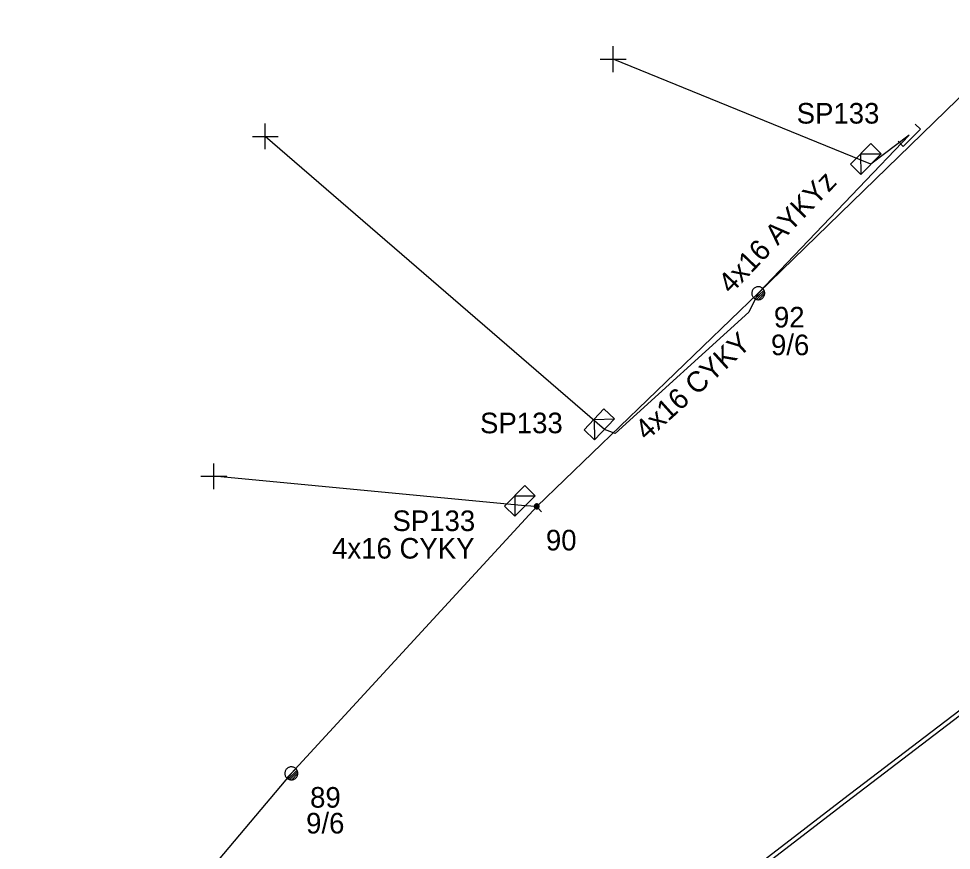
# Model space of a CAD drawing. Extents: x -748492 to -735633, y -1146251 to -1139940.
# Drawn here: x -742254.66 to -742209.4, y -1141162.91 to -1141122.53 of the extents above; entities that cross this region are included whole.
import ezdxf

# ---------------------------------------------------------------- set-up
doc = ezdxf.new("R2010")
doc.units = 0
for name, color, linetype in [('Vrstva 1', 7, 'Continuous'), ('Vrstva 12', 7, 'Continuous'), ('Vrstva 13', 7, 'Continuous'), ('Vrstva 14', 7, 'Continuous'), ('Vrstva 2', 7, 'Continuous'), ('Vrstva 31', 7, 'Continuous'), ('Vrstva 33', 7, 'Continuous'), ('Vrstva 34', 7, 'Continuous'), ('Vrstva 5', 7, 'Continuous'), ('Vrstva 52', 7, 'Continuous'), ('Vrstva 54', 7, 'Continuous'), ('Vrstva 55', 7, 'Continuous'), ('Vrstva 59', 7, 'Continuous'), ('Vrstva 9', 7, 'Continuous')]:
    doc.layers.add(name, color=color, linetype=linetype)

# ---------------------------------------------------------------- blocks, each defined once
blk = doc.blocks.new('NN440')
at = {"layer": 'Vrstva 2'}
for points in [[(0.631, -0.004), (0.627, 0.062), (0.617, 0.127), (0.6, 0.191), (0.577, 0.252), (0.547, 0.311), (0.511, 0.366), (0.469, 0.417), (0.423, 0.464), (0.371, 0.505), (0.316, 0.542), (0.257, 0.571), (0.196, 0.595), (0.132, 0.612), (0.067, 0.622), (0.001, 0.626), (-0.065, 0.622), (-0.13, 0.612), (-0.194, 0.595), (-0.255, 0.571), (-0.314, 0.542), (-0.369, 0.505), (-0.42, 0.464), (-0.467, 0.417), (-0.509, 0.366), (-0.544, 0.311), (-0.574, 0.252), (-0.598, 0.191), (-0.615, 0.127), (-0.626, 0.062), (-0.629, -0.004), (-0.626, -0.07), (-0.615, -0.135), (-0.598, -0.199), (-0.574, -0.26), (-0.544, -0.319), (-0.509, -0.374), (-0.467, -0.426), (-0.42, -0.472), (-0.369, -0.514), (-0.314, -0.55), (-0.255, -0.58), (-0.194, -0.603), (-0.13, -0.62), (-0.065, -0.631), (0.001, -0.634), (0.067, -0.631), (0.132, -0.62), (0.196, -0.603), (0.257, -0.58), (0.316, -0.55), (0.371, -0.514), (0.423, -0.472), (0.469, -0.426), (0.511, -0.374), (0.547, -0.319), (0.577, -0.26), (0.6, -0.199), (0.617, -0.135), (0.627, -0.07), (0.631, -0.004)], [(-0.631, 0), (0.629, 0)], [(-0.601, -0.177), (0.57, -0.177)], [(-0.513, -0.325), (0.501, -0.325)], [(-0.375, -0.473), (0.353, -0.473)]]:
    blk.add_lwpolyline(points, dxfattribs=at)
blk = doc.blocks.new('NN800')
at = {"layer": 'Vrstva 1'}
for points in [[(-0.442, 0.442), (0.442, -0.442)], [(-0.442, -0.442), (0.442, 0.442)]]:
    blk.add_lwpolyline(points, dxfattribs=at)
blk = doc.blocks.new('NN630')
at = {"layer": 'Vrstva 9'}
for points in [[(-0.003, -0.7), (-0.703, 0)], [(-0.703, -0.7), (-0.703, 0), (0.697, 0), (0.697, -0.7)], [(-0.003, -0.7), (0.697, 0)], [(-0.703, -0.7), (0.697, -0.7)]]:
    blk.add_lwpolyline(points, dxfattribs=at)
blk = doc.blocks.new('NN500')
at = {"layer": 'Vrstva 2'}
for points in [[(-0.001, -0.235), (0.023, -0.234), (0.048, -0.23), (0.071, -0.224), (0.094, -0.215), (0.116, -0.204), (0.137, -0.191), (0.156, -0.175), (0.173, -0.158), (0.189, -0.139), (0.202, -0.118), (0.213, -0.096), (0.222, -0.073), (0.229, -0.049), (0.232, -0.025), (0.234, 0), (0.232, 0.024), (0.229, 0.048), (0.222, 0.072), (0.213, 0.095), (0.202, 0.117), (0.189, 0.138), (0.173, 0.157), (0.156, 0.174), (0.137, 0.19), (0.116, 0.203), (0.094, 0.214), (0.071, 0.223), (0.048, 0.229), (0.023, 0.233), (-0.001, 0.235), (-0.026, 0.233), (-0.05, 0.229), (-0.074, 0.223), (-0.097, 0.214), (-0.119, 0.203), (-0.139, 0.19), (-0.158, 0.174), (-0.176, 0.157), (-0.191, 0.138), (-0.205, 0.117), (-0.216, 0.095), (-0.225, 0.072), (-0.231, 0.048), (-0.235, 0.024), (-0.236, 0), (-0.235, -0.025), (-0.231, -0.049), (-0.225, -0.073), (-0.216, -0.096), (-0.205, -0.118), (-0.191, -0.139), (-0.176, -0.158), (-0.158, -0.175), (-0.139, -0.191), (-0.119, -0.204), (-0.097, -0.215), (-0.074, -0.224), (-0.05, -0.23), (-0.026, -0.234), (-0.001, -0.235)], [(-0.001, -0.235), (0.023, -0.234), (0.048, -0.23), (0.071, -0.224), (0.094, -0.215), (0.116, -0.204), (0.137, -0.191), (0.156, -0.175), (0.173, -0.158), (0.189, -0.139), (0.202, -0.118), (0.213, -0.096), (0.222, -0.073), (0.229, -0.049), (0.232, -0.025), (0.234, 0), (0.232, 0.024), (0.229, 0.048), (0.222, 0.072), (0.213, 0.095), (0.202, 0.117), (0.189, 0.138), (0.173, 0.157), (0.156, 0.174), (0.137, 0.19), (0.116, 0.203), (0.094, 0.214), (0.071, 0.223), (0.048, 0.229), (0.023, 0.233), (-0.001, 0.235), (-0.026, 0.233), (-0.05, 0.229), (-0.074, 0.223), (-0.097, 0.214), (-0.119, 0.203), (-0.139, 0.19), (-0.158, 0.174), (-0.176, 0.157), (-0.191, 0.138), (-0.205, 0.117), (-0.216, 0.095), (-0.225, 0.072), (-0.231, 0.048), (-0.235, 0.024), (-0.236, 0), (-0.235, -0.025), (-0.231, -0.049), (-0.225, -0.073), (-0.216, -0.096), (-0.205, -0.118), (-0.191, -0.139), (-0.176, -0.158), (-0.158, -0.175), (-0.139, -0.191), (-0.119, -0.204), (-0.097, -0.215), (-0.074, -0.224), (-0.05, -0.23), (-0.026, -0.234), (-0.001, -0.235)], [(-0.001, -0.206), (0.02, -0.205), (0.041, -0.201), (0.062, -0.196), (0.082, -0.188), (0.101, -0.178), (0.12, -0.167), (0.136, -0.153), (0.151, -0.138), (0.165, -0.121), (0.177, -0.103), (0.186, -0.084), (0.194, -0.064), (0.2, -0.043), (0.203, -0.022), (0.204, 0), (0.203, 0.021), (0.2, 0.042), (0.194, 0.063), (0.186, 0.083), (0.177, 0.102), (0.165, 0.12), (0.151, 0.137), (0.136, 0.152), (0.12, 0.166), (0.101, 0.177), (0.082, 0.187), (0.062, 0.195), (0.041, 0.2), (0.02, 0.204), (-0.001, 0.205), (-0.023, 0.204), (-0.044, 0.2), (-0.065, 0.195), (-0.085, 0.187), (-0.104, 0.177), (-0.122, 0.166), (-0.139, 0.152), (-0.154, 0.137), (-0.167, 0.12), (-0.179, 0.102), (-0.189, 0.083), (-0.197, 0.063), (-0.202, 0.042), (-0.205, 0.021), (-0.207, 0), (-0.205, -0.022), (-0.202, -0.043), (-0.197, -0.064), (-0.189, -0.084), (-0.179, -0.103), (-0.167, -0.121), (-0.154, -0.138), (-0.139, -0.153), (-0.122, -0.167), (-0.104, -0.178), (-0.085, -0.188), (-0.065, -0.196), (-0.044, -0.201), (-0.023, -0.205), (-0.001, -0.206)], [(-0.001, -0.176), (0.017, -0.175), (0.035, -0.172), (0.053, -0.168), (0.07, -0.161), (0.087, -0.153), (0.102, -0.143), (0.116, -0.131), (0.129, -0.118), (0.141, -0.104), (0.151, -0.088), (0.159, -0.072), (0.166, -0.055), (0.171, -0.037), (0.174, -0.019), (0.175, 0), (0.174, 0.018), (0.171, 0.036), (0.166, 0.054), (0.159, 0.071), (0.151, 0.087), (0.141, 0.103), (0.129, 0.117), (0.116, 0.13), (0.102, 0.142), (0.087, 0.152), (0.07, 0.16), (0.053, 0.167), (0.035, 0.172), (0.017, 0.174), (-0.001, 0.175), (-0.02, 0.174), (-0.038, 0.172), (-0.056, 0.167), (-0.073, 0.16), (-0.089, 0.152), (-0.105, 0.142), (-0.119, 0.13), (-0.132, 0.117), (-0.143, 0.103), (-0.153, 0.087), (-0.162, 0.071), (-0.168, 0.054), (-0.173, 0.036), (-0.176, 0.018), (-0.177, 0), (-0.176, -0.019), (-0.173, -0.037), (-0.168, -0.055), (-0.162, -0.072), (-0.153, -0.088), (-0.143, -0.104), (-0.132, -0.118), (-0.119, -0.131), (-0.105, -0.143), (-0.089, -0.153), (-0.073, -0.161), (-0.056, -0.168), (-0.038, -0.172), (-0.02, -0.175), (-0.001, -0.176)], [(-0.001, -0.147), (0.014, -0.146), (0.029, -0.143), (0.044, -0.139), (0.058, -0.134), (0.072, -0.127), (0.085, -0.119), (0.097, -0.109), (0.107, -0.098), (0.117, -0.086), (0.125, -0.073), (0.132, -0.06), (0.138, -0.046), (0.142, -0.031), (0.144, -0.016), (0.145, 0), (0.144, 0.015), (0.142, 0.03), (0.138, 0.045), (0.132, 0.059), (0.125, 0.073), (0.117, 0.086), (0.107, 0.097), (0.097, 0.108), (0.085, 0.118), (0.072, 0.126), (0.058, 0.133), (0.044, 0.139), (0.029, 0.143), (0.014, 0.145), (-0.001, 0.146), (-0.017, 0.145), (-0.032, 0.143), (-0.046, 0.139), (-0.061, 0.133), (-0.074, 0.126), (-0.087, 0.118), (-0.099, 0.108), (-0.11, 0.097), (-0.119, 0.086), (-0.128, 0.073), (-0.135, 0.059), (-0.14, 0.045), (-0.144, 0.03), (-0.147, 0.015), (-0.147, 0), (-0.147, -0.016), (-0.144, -0.031), (-0.14, -0.046), (-0.135, -0.06), (-0.128, -0.073), (-0.119, -0.086), (-0.11, -0.098), (-0.099, -0.109), (-0.087, -0.119), (-0.074, -0.127), (-0.061, -0.134), (-0.046, -0.139), (-0.032, -0.143), (-0.017, -0.146), (-0.001, -0.147)], [(-0.001, -0.117), (0.011, -0.116), (0.023, -0.114), (0.035, -0.111), (0.046, -0.107), (0.057, -0.101), (0.067, -0.095), (0.077, -0.087), (0.085, -0.078), (0.093, -0.069), (0.1, -0.059), (0.105, -0.048), (0.11, -0.036), (0.113, -0.025), (0.115, -0.013), (0.115, 0), (0.115, 0.012), (0.113, 0.024), (0.11, 0.036), (0.105, 0.047), (0.1, 0.058), (0.093, 0.068), (0.085, 0.078), (0.077, 0.086), (0.067, 0.094), (0.057, 0.101), (0.046, 0.106), (0.035, 0.11), (0.023, 0.114), (0.011, 0.116), (-0.001, 0.116), (-0.013, 0.116), (-0.025, 0.114), (-0.037, 0.11), (-0.049, 0.106), (-0.059, 0.101), (-0.07, 0.094), (-0.079, 0.086), (-0.088, 0.078), (-0.096, 0.068), (-0.102, 0.058), (-0.108, 0.047), (-0.112, 0.036), (-0.115, 0.024), (-0.117, 0.012), (-0.118, 0), (-0.117, -0.013), (-0.115, -0.025), (-0.112, -0.036), (-0.108, -0.048), (-0.102, -0.059), (-0.096, -0.069), (-0.088, -0.078), (-0.079, -0.087), (-0.07, -0.095), (-0.059, -0.101), (-0.049, -0.107), (-0.037, -0.111), (-0.025, -0.114), (-0.013, -0.116), (-0.001, -0.117)], [(-0.001, -0.087), (0.008, -0.087), (0.017, -0.085), (0.026, -0.083), (0.034, -0.08), (0.042, -0.076), (0.05, -0.071), (0.057, -0.065), (0.063, -0.059), (0.069, -0.051), (0.074, -0.044), (0.078, -0.036), (0.081, -0.027), (0.084, -0.019), (0.085, -0.01), (0.086, 0), (0.085, 0.009), (0.084, 0.018), (0.081, 0.026), (0.078, 0.035), (0.074, 0.043), (0.069, 0.051), (0.063, 0.058), (0.057, 0.064), (0.05, 0.07), (0.042, 0.075), (0.034, 0.079), (0.026, 0.082), (0.017, 0.085), (0.008, 0.086), (-0.001, 0.087), (-0.01, 0.086), (-0.019, 0.085), (-0.028, 0.082), (-0.037, 0.079), (-0.045, 0.075), (-0.052, 0.07), (-0.059, 0.064), (-0.066, 0.058), (-0.072, 0.051), (-0.077, 0.043), (-0.081, 0.035), (-0.084, 0.026), (-0.086, 0.018), (-0.088, 0.009), (-0.088, 0), (-0.088, -0.01), (-0.086, -0.019), (-0.084, -0.027), (-0.081, -0.036), (-0.077, -0.044), (-0.072, -0.052), (-0.066, -0.059), (-0.059, -0.065), (-0.052, -0.071), (-0.045, -0.076), (-0.037, -0.08), (-0.028, -0.083), (-0.019, -0.085), (-0.01, -0.087), (-0.001, -0.087)], [(-0.001, -0.058), (0.005, -0.057), (0.011, -0.056), (0.016, -0.055), (0.022, -0.053), (0.027, -0.05), (0.032, -0.047), (0.037, -0.043), (0.041, -0.039), (0.045, -0.034), (0.048, -0.029), (0.051, -0.024), (0.053, -0.018), (0.055, -0.012), (0.056, -0.006), (0.056, 0), (0.056, 0.006), (0.055, 0.011), (0.053, 0.017), (0.051, 0.023), (0.048, 0.028), (0.045, 0.033), (0.041, 0.038), (0.037, 0.042), (0.032, 0.046), (0.027, 0.049), (0.022, 0.052), (0.016, 0.054), (0.011, 0.056), (0.005, 0.057), (-0.001, 0.057), (-0.007, 0.057), (-0.013, 0.056), (-0.019, 0.054), (-0.025, 0.052), (-0.03, 0.049), (-0.035, 0.046), (-0.04, 0.042), (-0.044, 0.038), (-0.048, 0.033), (-0.051, 0.028), (-0.054, 0.023), (-0.056, 0.017), (-0.057, 0.011), (-0.058, 0.006), (-0.059, 0), (-0.058, -0.006), (-0.057, -0.012), (-0.056, -0.018), (-0.054, -0.024), (-0.051, -0.029), (-0.048, -0.034), (-0.044, -0.039), (-0.04, -0.043), (-0.035, -0.047), (-0.03, -0.05), (-0.025, -0.053), (-0.019, -0.055), (-0.013, -0.056), (-0.007, -0.057), (-0.001, -0.058)], [(-0.001, -0.028), (0.002, -0.028), (0.005, -0.028), (0.007, -0.027), (0.01, -0.026), (0.013, -0.024), (0.015, -0.023), (0.017, -0.021), (0.019, -0.019), (0.021, -0.017), (0.023, -0.014), (0.024, -0.012), (0.025, -0.009), (0.026, -0.006), (0.026, -0.003), (0.027, 0), (0.026, 0.002), (0.026, 0.005), (0.025, 0.008), (0.024, 0.011), (0.023, 0.013), (0.021, 0.016), (0.019, 0.018), (0.017, 0.02), (0.015, 0.022), (0.013, 0.024), (0.01, 0.025), (0.007, 0.026), (0.005, 0.027), (0.002, 0.027), (-0.001, 0.027), (-0.004, 0.027), (-0.007, 0.027), (-0.01, 0.026), (-0.012, 0.025), (-0.015, 0.024), (-0.018, 0.022), (-0.02, 0.02), (-0.022, 0.018), (-0.024, 0.016), (-0.025, 0.013), (-0.027, 0.011), (-0.028, 0.008), (-0.028, 0.005), (-0.029, 0.002), (-0.029, 0), (-0.029, -0.003), (-0.028, -0.006), (-0.028, -0.009), (-0.027, -0.012), (-0.025, -0.014), (-0.024, -0.017), (-0.022, -0.019), (-0.02, -0.021), (-0.018, -0.023), (-0.015, -0.024), (-0.012, -0.026), (-0.01, -0.027), (-0.007, -0.028), (-0.004, -0.028), (-0.001, -0.028)], [(0.234, 0), (0.704, 0)]]:
    blk.add_lwpolyline(points, dxfattribs=at)
blk = doc.blocks.new('NN515')
at = {"layer": 'Vrstva 2'}
for points in [[(-0.59, 0.176), (0.591, 0.176)], [(-0.59, 0.176), (-0.59, -0.179)], [(0.591, 0.176), (0.591, -0.179)]]:
    blk.add_lwpolyline(points, dxfattribs=at)

msp = doc.modelspace()

# ---------------------------------------------------------------- linework, layer by layer
at = {"layer": 'Vrstva 1'}
msp.add_lwpolyline([(-742134.89, -1141032.84), (-742148.5, -1141063.89), (-742168.47, -1141086.19), (-742199.44, -1141117.05), (-742218.77, -1141135.86), (-742229.52, -1141146.21), (-742241.43, -1141159.17), (-742254.662, -1141174.889)], dxfattribs=at)
at = {"layer": 'Vrstva 5'}
for points in [[(-742235.763, -1141176.551), (-742234.298, -1141175.269), (-742227.291, -1141170.401), (-742214.489, -1141160.549), (-742201.36, -1141150.54), (-742190.92, -1141142.71), (-742179.875, -1141134.239), (-742165.992, -1141133.92), (-742150.784, -1141131.929), (-742137.144, -1141129.329), (-742129.869, -1141128.341), (-742126.457, -1141128.728), (-742117.009, -1141133.027), (-742105.982, -1141140.523), (-742101.438, -1141141.681), (-742082.991, -1141140.029), (-742072.635, -1141137.017), (-742065.368, -1141135.31), (-742057.936, -1141135.272)], [(-742235.464, -1141176.023), (-742234.422, -1141175.111), (-742227.409, -1141170.239), (-742214.611, -1141160.391), (-742201.48, -1141150.38), (-742191.04, -1141142.55), (-742179.945, -1141134.041), (-742166.008, -1141133.72), (-742150.816, -1141131.731), (-742137.176, -1141129.131), (-742129.871, -1141128.139), (-742126.403, -1141128.532), (-742116.911, -1141132.853), (-742105.898, -1141140.337), (-742101.422, -1141141.479), (-742083.029, -1141139.831), (-742072.685, -1141136.823), (-742065.392, -1141135.11), (-742057.627, -1141135.07), (-742057.209, -1141135.093)]]:
    msp.add_lwpolyline(points, dxfattribs=at)
at = {"layer": 'Vrstva 52'}
for points in [[(-742218.77, -1141135.86), (-742219.23, -1141136.78), (-742225.71, -1141142.67), (-742226.23, -1141142.47)], [(-742229.52, -1141146.21), (-742230.09, -1141146.19)]]:
    msp.add_lwpolyline(points, dxfattribs=at)
at = {"layer": 'Vrstva 54'}
msp.add_lwpolyline([(-742218.77, -1141135.86), (-742211.44, -1141128.19), (-742213.3, -1141129.59)], dxfattribs=at)
at = {"layer": 'Vrstva 59'}
for points in [[(-742213.3, -1141129.59), (-742225.81, -1141124.5)], [(-742226.23, -1141142.47), (-742242.69, -1141128.25)], [(-742230.09, -1141146.19), (-742245.19, -1141144.75)]]:
    msp.add_lwpolyline(points, dxfattribs=at)

# ---------------------------------------------------------------- block references
at = {"layer": 'Vrstva 13', "rotation": -135.10486370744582}
msp.add_blockref('NN515', (-742211.44, -1141128.19), dxfattribs=at)
at = {"layer": 'Vrstva 13'}
for name, p, xscale, yscale, rotation in [('NN440', (-742218.77, -1141135.86), 0.5, 0.5000000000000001, 43.731300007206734), ('NN500', (-742229.52, -1141146.21), 0.49999999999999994, 0.5000000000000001, -50.11040096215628), ('NN440', (-742241.43, -1141159.17), 0.5, 0.5, 45.34207512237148)]:
    msp.add_blockref(name, p, dxfattribs=dict(at, xscale=xscale, yscale=yscale, rotation=rotation))
at = {"layer": 'Vrstva 31'}
for p, rotation in [((-742213.3, -1141129.59), -134.21919832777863), ((-742226.23, -1141142.47), -133.2454417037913), ((-742230.09, -1141146.19), -134.65792497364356)]:
    msp.add_blockref('NN630', p, dxfattribs=dict(at, rotation=rotation))
at = {"layer": 'Vrstva 34'}
for p, rotation in [((-742225.81, -1141124.5), 45), ((-742242.69, -1141128.25), 44.99999995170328), ((-742245.19, -1141144.75), 44.99999995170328)]:
    msp.add_blockref('NN800', p, dxfattribs=dict(at, rotation=rotation))

# ---------------------------------------------------------------- texts
at = {"layer": 'Vrstva 12'}
for rotation, p in [(359.975, (-742218.149, -1141138.869)), (0.043, (-742240.711, -1141162.09))]:
    msp.add_text('9/6', height=1, rotation=rotation, dxfattribs=at).set_placement(p)
at = {"layer": 'Vrstva 14'}
for s, rotation, p in [('92', 359.971, (-742218.008, -1141137.524)), ('90', 359.952, (-742229.073, -1141148.347)), ('89', 359.957, (-742240.517, -1141160.835))]:
    msp.add_text(s, height=1, rotation=rotation, dxfattribs=at).set_placement(p)
at = {"layer": 'Vrstva 33'}
for rotation, p in [(0.008, (-742216.904, -1141127.626)), (0.045, (-742232.27, -1141142.661)), (359.963, (-742236.52, -1141147.406))]:
    msp.add_text('SP133', height=1, rotation=rotation, dxfattribs=at).set_placement(p)
at = {"layer": 'Vrstva 54'}
for rotation, p in [(42.138, (-742224.188, -1141143.055)), (0.011, (-742239.451, -1141148.744))]:
    msp.add_text('4x16 CYKY', height=1, rotation=rotation, dxfattribs=at).set_placement(p)
at = {"layer": 'Vrstva 55'}
msp.add_text('4x16 AYKYz', height=1, rotation=46.245, dxfattribs=at).set_placement((-742220.09, -1141135.939))

doc.saveas('drawing.dxf')
